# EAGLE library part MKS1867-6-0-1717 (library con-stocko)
Serie MKS 1850 Lötstifte In-line, Raster 2.5 mm, Stiftwannen, stehend, mit Rastlasche Source: http://www.stocko.de/de/index.php?seite=ka_rfk2_mks1850.html&rubrik=Katalog+-+RFK+2 rfk_1850.pdf
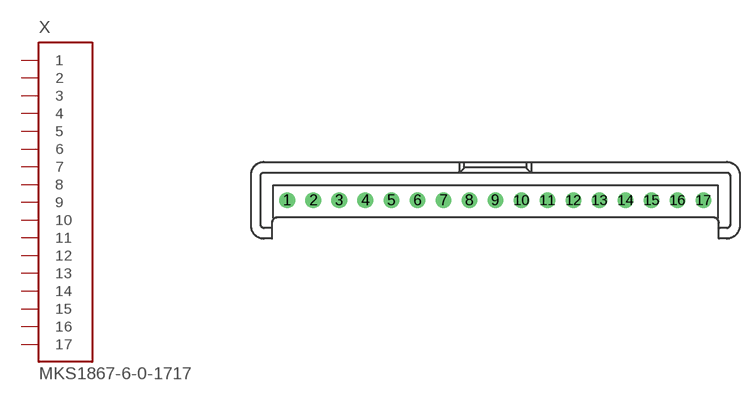
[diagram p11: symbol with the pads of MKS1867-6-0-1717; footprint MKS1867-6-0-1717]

Designator prefix X

## MKS1867-6-0-1717 (OC_FARNELL: unknown; OC_NEWARK: unknown)  [MKS1867-6-0-1717]
1  1  in
2  2  in
3  3  in
4  4  in
5  5  in
6  6  in
7  7  in
8  8  in
9  9  in
10  10  in
11  11  in
12  12  in
13  13  in
14  14  in
15  15  in
16  16  in
17  17  in

## Footprint MKS1867-6-0-1717 (pad centres in mm)
Serie MKS 1850 Lötstifte In-line, Raster 2.5 mm, Stiftwannen, stehend, mit Rastlasche Source: http://www.stocko.de/de/index.php?seite=ka_rfk2_mks1850.html&rubrik=Katalog+-+RFK+2 rfk_1850.pdf
drill 1 pad 1.422 round: 1 -20,0; 2 -17.5,0; 3 -15,0; 4 -12.5,0; 5 -10,0; 6 -7.5,0; 7 -5,0; 8 -2.5,0; 9 0,0; 10 2.5,0; 11 5,0; 12 7.5,0; 13 10,0; 14 12.5,0; 15 15,0; 16 17.5,0; 17 20,0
